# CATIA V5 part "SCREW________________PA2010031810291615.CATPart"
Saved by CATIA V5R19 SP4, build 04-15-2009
Part number: SCREW________________PA2010031810291615
Bounding box of the stored display mesh (mm): x -2.742 to 2.742, y -2.75 to 2.75, z -16 to 2
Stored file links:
  E:\CadInnWork\InWork\SCREW________________PA2010031810291615.CATPart
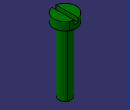
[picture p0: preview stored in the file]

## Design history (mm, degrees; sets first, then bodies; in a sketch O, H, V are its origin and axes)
Parameters
  Update = false
  PDM_version = "A"
  PDM_iteration = 1
  PDM_owner = "moren                    "
  PDM_comment = ""
  PDM_partnumber = "PA002170EA6A57201003181029160015"
Body1 (main body)
  Sketch1 on yz-plane, origin (0, 0, 0), H (0, 1, 0), V (0, 0, 1)
    axis line L1 (0, 73.7857) -> (0, -77.8237)
    point P1 (0, 73.7857)
    point P3 (0, 2)
    line L2 (0, 2) -> (2.75, 2)
    line L3 (2.75, 2) -> (2.75, 0)
    point P5 (2.75, 0)
    line L4 (2.75, 0) -> (1.5, 0)
    line L5 (1.5, 0) -> (1.5, -16)
    line L6 (1.5, -16) -> (0, -16)
    point P8 (0, -16)
    "Radius" L5 L1 = 1.5
    "Radius" L3 L1 = 2.75
    length L3 = 2
    distance L4 L6 = 16
    coincidence: P1 V, P3 L1, P5 H, P8 L1
    vertical: L1 V, L3 V, L5 V
    horizontal: L2 H, L4 H, L6 H
  Shaft1: profile Sketch1, axis Sketch1.L1, angle 360
  Chamfer1: length 0.25, angle 45, on edge [face of Shaft1 from Sketch1.L5 | face of Shaft1 from Sketch1.L6]
  Sketch2 on zx-plane, origin (0, 0, 0), H (-1, 0, 0), V (0, 0, 1)
    line L1 (-0.5, 3.7732) -> (0.5, 3.7732)
    line L2 (0.5, 3.7732) -> (0.5, 1)
    line L3 (0.5, 1) -> (-0.5, 1)
    line L4 (-0.5, 1) -> (-0.5, 3.7732)
    distance L3 H = 1
    length L1 = 1
    horizontal: L1 H, L3 H
    vertical: L2 V, L4 V
    symmetry: L2 L4 V
  Pocket1: profile Sketch2, direction (0, -1, 0), through (limit type 3), opposite side through (limit type 3)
